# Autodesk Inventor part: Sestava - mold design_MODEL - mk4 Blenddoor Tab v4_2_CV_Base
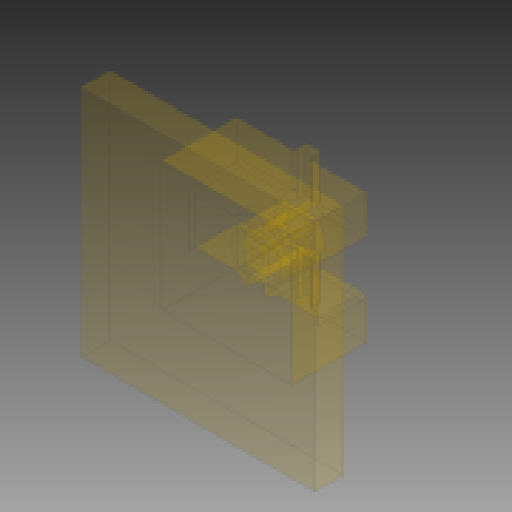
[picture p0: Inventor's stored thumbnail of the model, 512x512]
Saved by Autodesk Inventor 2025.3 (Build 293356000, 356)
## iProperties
Part Number: Sestava - mold design_MODEL - mk4 Blenddoor Tab v4_2_CV_Base
Material: Generický
Document SubType Name: Modelování
Designer: Patrik
Appearance: Výchozí
Author: Patrik
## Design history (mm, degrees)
node "Sestava - mold design_MODEL - mk4 Blenddoor Tab v4_2_MP"
node "Pracovní rovina1"
sketch "Náčrt4"
  geometry: L1 (2.925, -4.147)-(-8.225, -4.147) reference; L2 (-8.225, -17.257)-(2.925, -17.257) reference; L3 (-6.675, -10.002)-(-6.675, -6.227) reference; L4 (-6.675, -6.227)-(1.375, -6.227) reference; L5 (1.375, -6.227)-(1.375, -10.002) reference; L6 (1.375, -11.402)-(1.375, -15.177) reference; L7 (1.375, -15.177)-(-6.675, -15.177) reference; L8 (-6.675, -15.177)-(-6.675, -11.402) reference; L9 (19.85, -18.702)-(19.85, -2.702); L10 (-25.15, -2.702)-(-25.15, -18.702); L11 (-25.15, -18.702)-(19.85, -2.702); L12 (19.85, -18.702)-(-25.15, -2.702); L13 (2.925, -17.257)-(2.925, -18.702); L14 (2.925, -4.147)-(2.925, -2.702); L15 (-8.225, -4.147)-(-8.225, -2.702); L16 (-8.225, -17.257)-(-8.225, -18.702); L17 (19.85, -2.702)-(2.925, -2.702); L18 (-8.225, -2.702)-(-25.15, -2.702); L19 (-25.15, -18.702)-(-8.225, -18.702); L20 (2.925, -18.702)-(19.85, -18.702); L21 (19.85, 0)-(19.85, -21.404) reference; L22 (-25.15, -21.404)-(-25.15, 0) reference; C1 r 1.25 at (-2.65, -10.702) reference; A1 r 8.605 centre (-2.65, -10.702) between (2.925, -17.257) and (2.925, -4.147) reference; A2 r 8.605 centre (-2.65, -10.702) between (-8.225, -4.147) and (-8.225, -17.257) reference; A3 r 0.7 centre (-6.675, -10.702) between (-6.675, -10.002) and (-6.675, -11.402) reference; A4 r 0.7 centre (1.375, -10.702) between (1.375, -11.402) and (1.375, -10.002) reference; 1 further point
  constraints: 24 end point, 6 perpendicular, 5 parallel, 2 collinear, 2 horizontal, 2 midpoint, 2 point on line
  dimensions: "d17" = 16 distance between parallel lines of L20 L17
extrude "Vysunutí4" cut sketch "Náčrt4" stored distance "d12" = 10; taper "d13" = 0 deg
chamfer "Zkosení2" distance "d14" = 1.25; stored, may be unused: second distance "d15" = 1.25, angle "d16" = 45 deg
sketch "Náčrt5"
  geometry: L1 (17.761, -31.363)-(18.123, -31.529) reference; L2 (19.158, -31.144)-(19.324, -30.782) reference; L3 (18.939, -29.747)-(18.577, -29.581) reference; L4 (17.542, -29.966)-(17.376, -30.328) reference; L5 (25.67, -14.246)-(25.67, -14.644) reference; L6 (26.451, -15.425)-(26.849, -15.425) reference; L7 (27.63, -14.644)-(27.63, -14.246) reference; L8 (26.849, -13.465)-(26.451, -13.465) reference; L9 (0, -45)-(0, 0) reference; L10 (0, 0)-(45, 0) reference; L11 (45, 0)-(45, -45) reference; L12 (45, -45)-(0, -45) reference; L13 (-18, 18)-(-18, -63); L14 (-18, -63)-(63, -63); L15 (63, -63)-(63, 18); L16 (63, 18)-(-18, 18); A1 r 1 centre (18.35, -30.555) between (17.376, -30.328) and (17.761, -31.363) reference; A2 r 1 centre (18.35, -30.555) between (18.123, -31.529) and (19.158, -31.144) reference; A3 r 1 centre (18.35, -30.555) between (19.324, -30.782) and (18.939, -29.747) reference; A4 r 1 centre (18.35, -30.555) between (18.577, -29.581) and (17.542, -29.966) reference; A5 r 1 centre (26.65, -14.445) between (26.451, -13.465) and (25.67, -14.246) reference; A6 r 1 centre (26.65, -14.445) between (25.67, -14.644) and (26.451, -15.425) reference; A7 r 1 centre (26.65, -14.445) between (26.849, -15.425) and (27.63, -14.644) reference; A8 r 1 centre (26.65, -14.445) between (27.63, -14.246) and (26.849, -13.465) reference; 1 further point
  constraints: 32 end point, 16 point on circle, 8 centre point, 4 horizontal, 4 vertical, 43 other
  dimensions: "d18" = 18 distance between parallel lines of L9 L13
extrude "Vysunutí5" join sketch "Náčrt5" distance "d19" = 10; taper "d20" = 0 deg
chamfer "Zkosení3" distance "d21" = 0.5; stored, may be unused: second distance "d22" = 1.25, angle "d23" = 45 deg
node "Objemová tělesa"
node "Povrchová tělesa"
feature "Těleso8::Sestava - mold design_MODEL - mk4 Blenddoor Tab v4_"
tag "Prvek štítků3"
node "Promítnutá smyčka1"
node "Těleso8"
feature "Sestava - mold design_MODEL - mk4 Blenddoor Tab v4_2_MP_Těle"
